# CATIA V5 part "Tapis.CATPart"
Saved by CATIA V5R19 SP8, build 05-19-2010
Part number: Tapis
Nomenclature: 57
Material "Caoutchouc": density 910 kg/m3, Young's modulus 2e+06 Pa, Poisson ratio 0.49, thermal expansion 0.000162 1/K
Bounding box of the stored display mesh (mm): x -220 to 220, y -22.493 to 1252.453, z -84.046 to 22.472
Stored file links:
  C:\Users\rphgr\Desktop\0_Tapis_TC520B_vitesse\Tapis.CATPart
  D:\Documents\1_Travail\1 - ac-limoges.fr\ac-limoges.fr\Emmanuel Maynard - STI2D_Turgot\3 - Supports\Tapis de course TC520B\Tapis de course TC520B_Ca\0_Tapis_TC520B.CATProduct
  D:\Documents\1_Travail\1 - ac-limoges.fr\ac-limoges.fr\Emmanuel Maynard - STI2D_Turgot\3 - Supports\Tapis de course TC520B\Tapis de course TC520B_Ca\Tambour_Tendeur.CATPart
  D:\Documents\1_Travail\1 - ac-limoges.fr\ac-limoges.fr\Emmanuel Maynard - STI2D_Turgot\3 - Supports\Tapis de course TC520B\Tapis de course TC520B_Ca\Tambour_moteur.CATPart
  D:\Programmes\DassaultSysteme\win_b64\startup\materials\French\Catalog.CATMaterial
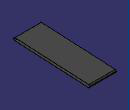
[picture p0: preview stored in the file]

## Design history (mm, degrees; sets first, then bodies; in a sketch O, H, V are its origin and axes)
AxisSystem1: origin (0, 0, 0), X (1, 0, 0), Y (0, 1, 0), Z (0, 0, 1)
Set1
  Sketch1 on YZ plane of AxisSystem1, origin (0, 0, 0), H (0, 1, 0), V (0, 0, 1)
    line L1 through (38.9366, 19.0771) direction (0.9987, -0.05)
    reference intersected line E1 (1231.0097, -40.6) -> (1.05, 20.9737) from face of Pad1
    coincidence: L1 E1
Set2
  DatumCurve1 to DatumCurve3
Body1 (main body), material "Caoutchouc"
  Sketch2 on YZ plane of AxisSystem1, origin (0, 0, 0), H (0, 1, 0), V (0, 0, 1)
    construction line L1 (0, 0) -> (1229.9597, -61.5738)
    point P1 (1229.9597, -61.5738)
    line L2 (1.05, 20.9737) -> (1231.0097, -40.6)
    line L3 (1228.9097, -82.5475) -> (-1.05, -20.9737)
    arc A1 centre (1229.9597, -61.5738) radius 21 from (1231.0097, -40.6) to (1228.9097, -82.5475) cw
    arc A2 centre (0, 0) radius 21 from (-1.05, -20.9737) to (1.05, 20.9737) cw
    reference projected point E1 (1229.9597, -61.5738) from edge of DatumCurve1
    reference projected circle E2 centre (0, 0) radius 21 from edge of DatumCurve2
    reference projected circle E3 centre (1229.9597, -61.5738) radius 21 from edge of DatumCurve3
    tangency: A1 L2, A2 L2, A1 L3, A2 L3
    coincidence: P1 E1, A2 E2, A1 E3
  Pad1: profile Sketch2, direction (1, 0, 0), length 220, mirrored extent, thin wall 0, second thickness 1.5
